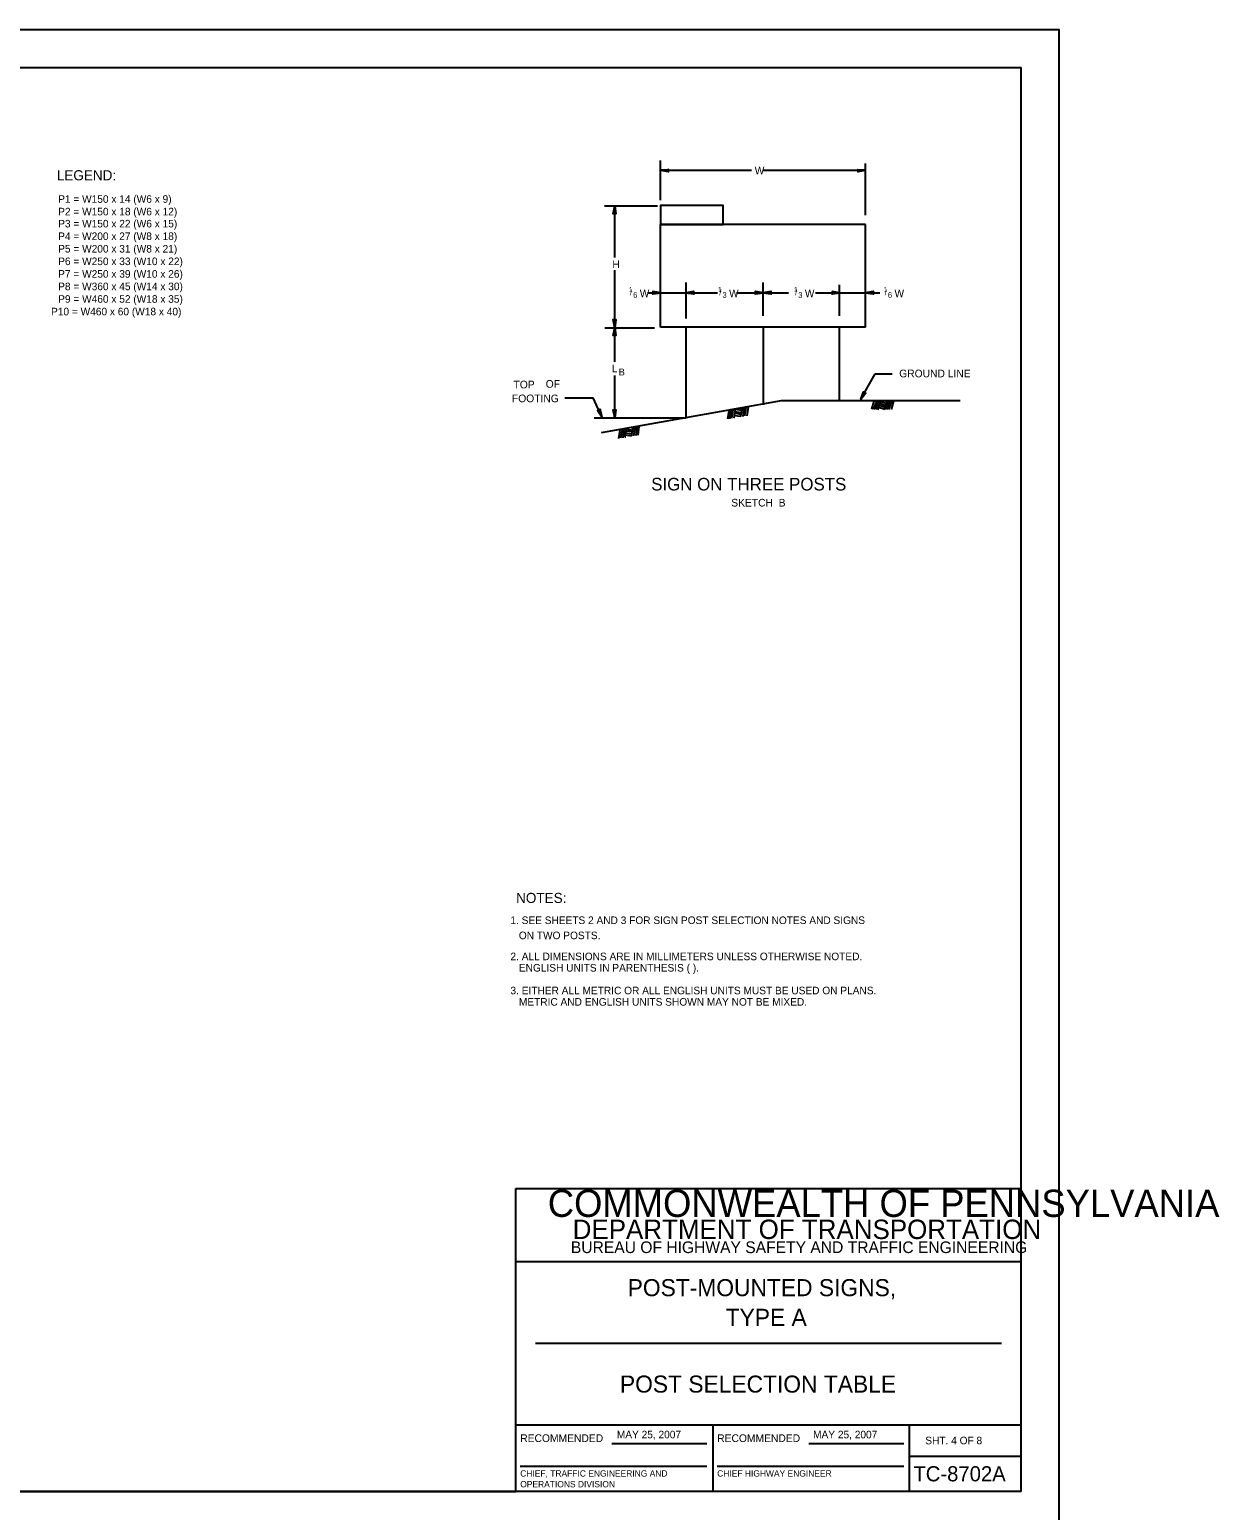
# Model space of a CAD drawing. Extents: x 637580 to 641008, y 294594 to 295782.
# Drawn here: x 640537 to 641008, y 295195 to 295782 of the extents above; entities that cross this region are included whole.
import ezdxf

# ---------------------------------------------------------------- set-up
doc = ezdxf.new("R2010")
doc.units = 0
for name, color, linetype in [('1', 7, 'Continuous'), ('2', 7, 'Continuous'), ('PLT-BNDY', 7, 'Continuous')]:
    doc.layers.add(name, color=color, linetype=linetype)

msp = doc.modelspace()

# ---------------------------------------------------------------- linework, layer by layer
at = {"layer": '1'}
for p, q in [((640143.31, 295766.63), (640929.31, 295766.63)), ((640929.31, 295202.63), (640929.31, 295766.63)), ((640786.58, 295714.03), (640786.58, 295729.78)), ((640786.58, 295725.9), (640822.58, 295725.9)), ((640827.21, 295725.9), (640867.71, 295725.9)), ((640867.71, 295708.15), (640867.71, 295728.65)), ((640764.33, 295711.78), (640785.33, 295711.78)), ((640768.46, 295691.4), (640768.46, 295711.78)), ((640786.58, 295663.78), (640786.58, 295704.4)), ((640867.71, 295704.4), (640786.58, 295704.4)), ((640867.71, 295663.78), (640867.71, 295704.4)), ((640768.46, 295663.53), (640768.46, 295686.4)), ((640796.71, 295667.15), (640796.71, 295681.4)), ((640827.21, 295668.28), (640827.21, 295681.4)), ((640857.46, 295668.28), (640857.46, 295680.53)), ((640781.33, 295677.4), (640786.58, 295677.4)), ((640786.58, 295677.4), (640796.21, 295677.4)), ((640796.71, 295677.4), (640809.08, 295677.4)), ((640816.58, 295677.4), (640827.21, 295677.4)), ((640827.21, 295677.4), (640837.21, 295677.4)), ((640847.96, 295677.4), (640857.46, 295677.4)), ((640857.46, 295677.4), (640867.71, 295677.4)), ((640867.71, 295677.4), (640873.46, 295677.4)), ((640764.46, 295663.53), (640784.21, 295663.53)), ((640768.46, 295650.03), (640768.46, 295663.53)), ((640867.71, 295663.78), (640786.58, 295663.78)), ((640796.71, 295627.9), (640796.71, 295663.78)), ((640827.21, 295663.78), (640827.21, 295633.03)), ((640857.46, 295634.4), (640857.46, 295663.78)), ((640768.46, 295627.9), (640768.46, 295644.65)), ((640865.83, 295635.28), (640871.58, 295645.28)), ((640871.58, 295645.28), (640878.33, 295645.28)), ((640748.71, 295635.78), (640759.83, 295635.78)), ((640763.33, 295628.28), (640759.83, 295635.78)), ((640834.33, 295634.53), (640763.08, 295621.9)), ((640816.08, 295631.28), (640815.58, 295627.9)), ((640818.71, 295631.65), (640818.21, 295628.4)), ((640818.71, 295631.4), (640818.33, 295631.53)), ((640819.58, 295631.9), (640819.08, 295628.4)), ((640820.33, 295631.9), (640819.83, 295628.65)), ((640821.21, 295632.15), (640820.71, 295628.65)), ((640905.21, 295634.53), (640834.33, 295634.53)), ((640871.08, 295634.4), (640870.08, 295631.28)), ((640872.08, 295634.4), (640870.83, 295631.15)), ((640872.83, 295634.4), (640871.71, 295631.15)), ((640873.71, 295634.4), (640872.46, 295631.15)), ((640872.96, 295631.15), (640872.58, 295631.28)), ((640875.33, 295631.15), (640872.83, 295631.9)), ((640875.46, 295631.9), (640873.08, 295632.78)), ((640875.71, 295632.65), (640873.46, 295633.53)), ((640876.08, 295633.4), (640873.71, 295634.28)), ((640876.33, 295634.4), (640875.33, 295631.15)), ((640876.33, 295634.28), (640875.83, 295634.4)), ((640877.08, 295634.4), (640876.08, 295631.15)), ((640878.08, 295634.4), (640876.83, 295631.15)), ((640878.83, 295634.4), (640877.83, 295631.15)), ((640760.33, 295627.9), (640796.71, 295627.9)), ((640813.58, 295630.78), (640813.08, 295627.4)), ((640814.33, 295631.03), (640813.83, 295627.53)), ((640815.21, 295631.03), (640814.71, 295627.78)), ((640815.96, 295628.03), (640815.58, 295628.03)), ((640818.33, 295628.4), (640815.71, 295628.65)), ((640818.33, 295629.15), (640815.83, 295629.65)), ((640818.46, 295629.9), (640815.96, 295630.28)), ((640818.58, 295630.78), (640816.08, 295631.15)), ((640770.46, 295623.03), (640769.96, 295619.65)), ((640771.33, 295623.15), (640770.71, 295619.78)), ((640772.08, 295623.4), (640771.58, 295619.9)), ((640772.96, 295623.53), (640772.33, 295620.15)), ((640772.83, 295620.15), (640772.46, 295620.15)), ((640775.08, 295620.65), (640772.58, 295621.03)), ((640775.08, 295621.4), (640772.71, 295621.78)), ((640775.33, 295622.28), (640772.83, 295622.53)), ((640775.46, 295622.9), (640772.96, 295623.4)), ((640775.58, 295623.9), (640774.96, 295620.65)), ((640775.58, 295623.9), (640775.08, 295623.9)), ((640776.33, 295624.03), (640775.83, 295620.78)), ((640777.21, 295624.28), (640776.71, 295620.9)), ((640777.96, 295624.4), (640777.58, 295621.03)), ((640729.31, 295202.63), (640729.31, 295322.63)), ((640729.31, 295322.63), (640929.31, 295322.63)), ((640929.31, 295293.63), (640729.31, 295293.63)), ((640737.06, 295261.31), (640921.56, 295261.31)), ((640729.31, 295229), (640929.31, 295229)), ((640807.31, 295229), (640807.31, 295202.63)), ((640885.19, 295202.63), (640885.19, 295229)), ((640767.24, 295221.57), (640804.87, 295221.57)), ((640845.24, 295221.57), (640882.87, 295221.57)), ((640885.19, 295216.63), (640929.31, 295216.63)), ((640730.99, 295212.68), (640804.87, 295212.68)), ((640808.99, 295212.68), (640882.87, 295212.68)), ((640929.31, 295202.63), (640143.31, 295202.63)), ((640143.31, 295202.63), (640729.31, 295202.63))]:
    msp.add_line(p, q, dxfattribs=at)
for points in [[(640789.58, 295725.4), (640789.33, 295725.65), (640786.58, 295725.9), (640789.58, 295725.4), (640789.71, 295725.28), (640786.58, 295725.9), (640789.33, 295725.9), (640789.46, 295726.03), (640786.58, 295725.9), (640789.71, 295726.28), (640789.46, 295726.03)], [(640864.71, 295726.03), (640864.83, 295725.9), (640867.71, 295725.9), (640864.71, 295726.03), (640864.71, 295726.28), (640867.71, 295725.9), (640864.83, 295725.65), (640864.83, 295725.4), (640867.71, 295725.9), (640864.71, 295725.28), (640864.83, 295725.4)], [(640767.96, 295708.9), (640768.21, 295708.9), (640768.46, 295711.78), (640767.96, 295708.9), (640767.83, 295708.65), (640768.46, 295711.78), (640768.58, 295708.9), (640768.71, 295708.9), (640768.46, 295711.78), (640768.83, 295708.65), (640768.71, 295708.9)], [(640783.58, 295677.9), (640783.71, 295677.65), (640786.58, 295677.4), (640783.58, 295677.9), (640783.46, 295677.9), (640786.58, 295677.4), (640783.71, 295677.28), (640783.58, 295677.03), (640786.58, 295677.4), (640783.46, 295676.9), (640783.58, 295677.03)], [(640799.58, 295677.03), (640799.46, 295677.28), (640796.71, 295677.4), (640799.58, 295677.03), (640799.71, 295676.9), (640796.71, 295677.4), (640799.46, 295677.65), (640799.58, 295677.9), (640796.71, 295677.4), (640799.71, 295677.9), (640799.58, 295677.9)], [(640824.21, 295677.9), (640824.33, 295677.65), (640827.21, 295677.4), (640824.21, 295677.9), (640824.08, 295677.9), (640827.21, 295677.4), (640824.33, 295677.28), (640824.21, 295677.03), (640827.21, 295677.4), (640824.08, 295676.9), (640824.21, 295677.03)], [(640830.21, 295677.03), (640829.96, 295677.28), (640827.21, 295677.4), (640830.21, 295677.03), (640830.33, 295676.9), (640827.21, 295677.4), (640829.96, 295677.65), (640830.21, 295677.9), (640827.21, 295677.4), (640830.33, 295677.9), (640830.21, 295677.9)], [(640854.58, 295677.9), (640854.71, 295677.65), (640857.46, 295677.4), (640854.58, 295677.9), (640854.46, 295677.9), (640857.46, 295677.4), (640854.71, 295677.28), (640854.58, 295677.03), (640857.46, 295677.4), (640854.46, 295676.9), (640854.58, 295677.03)], [(640870.71, 295677.03), (640870.58, 295677.28), (640867.71, 295677.4), (640870.71, 295677.03), (640870.83, 295676.9), (640867.71, 295677.4), (640870.58, 295677.65), (640870.71, 295677.9), (640867.71, 295677.4), (640870.83, 295677.9), (640870.71, 295677.9)], [(640768.83, 295666.53), (640768.58, 295666.4), (640768.46, 295663.53), (640768.83, 295666.53), (640768.83, 295666.78), (640768.46, 295663.53), (640768.21, 295666.4), (640767.96, 295666.53), (640768.46, 295663.53), (640767.83, 295666.78), (640767.96, 295666.53)], [(640767.96, 295660.65), (640768.21, 295660.78), (640768.46, 295663.53), (640767.96, 295660.65), (640767.83, 295660.53), (640768.46, 295663.53), (640768.58, 295660.78), (640768.71, 295660.65), (640768.46, 295663.53), (640768.83, 295660.53), (640768.71, 295660.65)], [(640867.71, 295637.65), (640867.33, 295637.65), (640865.83, 295635.28), (640867.71, 295637.65), (640867.83, 295637.65), (640865.83, 295635.28), (640867.08, 295637.78), (640866.96, 295638.03), (640865.83, 295635.28), (640866.96, 295638.15), (640866.96, 295638.03)], [(640762.46, 295631.03), (640762.33, 295630.78), (640763.33, 295628.28), (640762.46, 295631.03), (640762.46, 295631.28), (640763.33, 295628.28), (640762.08, 295630.65), (640761.71, 295630.65), (640763.33, 295628.28), (640761.58, 295630.78), (640761.71, 295630.65)], [(640768.83, 295630.9), (640768.58, 295630.78), (640768.46, 295627.9), (640768.83, 295630.9), (640768.83, 295631.03), (640768.46, 295627.9), (640768.21, 295630.78), (640767.96, 295630.78), (640768.46, 295627.9), (640767.83, 295631.03), (640767.96, 295630.78)]]:
    msp.add_lwpolyline(points, dxfattribs=at)
msp.add_lwpolyline([(640811.33, 295704.4), (640811.33, 295711.9), (640786.58, 295711.9), (640786.58, 295704.4)], close=True, dxfattribs=at)
at = {"layer": 'PLT-BNDY'}
msp.add_lwpolyline([(640103.31, 295781.63), (640944.31, 295781.63), (640944.31, 295187.63), (640103.31, 295187.63)], close=True, dxfattribs=at)

# ---------------------------------------------------------------- texts
at = {"layer": '1'}
for s, height, p in [('LEGEND:', 4.003, (640547.47, 295721.93)), ('W', 3.04, (640823.83, 295724.28)), ('P1 = W150 x 14 (W6 x 9)', 3, (640548, 295713.03)), ('P2 = W150 x 18 (W6 x 12)', 3, (640548, 295708.05)), ('P3 = W150 x 22 (W6 x 15)', 3, (640548, 295703.27)), ('P4 = W200 x 27 (W8 x 18)', 3, (640548, 295698.3)), ('P5 = W200 x 31 (W8 x 21)', 3, (640548, 295693.33)), ('P6 = W250 x 33 (W10 x 22)', 3, (640548, 295688.35)), ('H', 3.04, (640767.46, 295687.15)), ('P7 = W250 x 39 (W10 x 26)', 3, (640548, 295683.38)), ('P8 = W360 x 45 (W14 x 30)', 3, (640548, 295678.41)), ('1', 2, (640773.96, 295677.65)), ('/', 2.25, (640774.46, 295676.4)), ('W', 3, (640778.33, 295675.65)), ('1', 2, (640809.33, 295677.65)), ('/', 2.25, (640809.83, 295676.4)), ('W', 3, (640813.71, 295675.65)), ('1', 2, (640839.33, 295677.65)), ('/', 2.25, (640839.83, 295676.4)), ('W', 3, (640843.71, 295675.65)), ('1', 2, (640874.83, 295677.65)), ('/', 2.25, (640875.33, 295676.4)), ('W', 3, (640879.21, 295675.65)), ('P9 = W460 x 52 (W18 x 35)', 3, (640548, 295673.44)), ('6', 2.25, (640775.71, 295675.4)), ('3', 2.25, (640811.08, 295675.4)), ('3', 2.25, (640841.08, 295675.4)), ('6', 2.25, (640876.58, 295675.4)), ('P10 = W460 x 60 (W18 x 40)', 3, (640545.18, 295668.46)), ('L', 3.04, (640767.21, 295645.9)), ('B', 2.73, (640769.96, 295644.65)), ('GROUND LINE', 3.0427, (640881.08, 295643.9)), ('FOOTING', 3.044, (640727.71, 295634.03)), ('TOP', 3.043, (640728.33, 295639.53)), ('OF', 3.043, (640741.08, 295639.78)), ('SKETCH  B', 3.044, (640814.56, 295592.73)), (' 1. SEE SHEETS 2 AND 3 FOR SIGN POST SELECTION NOTES AND SIGNS', 3, (640725.97, 295427.37)), ('    ON TWO POSTS.', 3, (640725.97, 295421.37)), ('COMMONWEALTH OF PENNSYLVANIA', 10.7828, (640741.9, 295311.36)), ('DEPARTMENT OF TRANSPORTATION', 7.6837, (640751.76, 295302.61)), ('BUREAU OF HIGHWAY SAFETY AND TRAFFIC ENGINEERING', 4.6253, (640751.04, 295297.04)), ('POST-MOUNTED SIGNS,', 6.75, (640773.54, 295279.97)), ('TYPE A', 6.75, (640812.35, 295268.22)), ('POST SELECTION TABLE', 6.75, (640770.47, 295241.78)), ('RECOMMENDED', 3.048, (640730.99, 295222.2)), ('RECOMMENDED', 3.048, (640808.99, 295222.2)), ('SHT. 4 OF 8', 3, (640891.4, 295221.31)), ('CHIEF, TRAFFIC ENGINEERING AND', 2.5, (640730.99, 295208.51)), ('CHIEF HIGHWAY ENGINEER', 2.5, (640808.99, 295208.51)), ('TC-8702A', 6, (640886.68, 295206.63)), ('OPERATIONS DIVISION', 2.5, (640730.99, 295204.26))]:
    msp.add_text(s, height=height, dxfattribs=at).set_placement(p)
at = {"layer": '2'}
for s, height, p in [('SIGN ON THREE POSTS', 5, (640782.85, 295599.09)), ('NOTES:', 4.003, (640729.35, 295435.71)), (' 2. ALL DIMENSIONS ARE IN MILLIMETERS UNLESS OTHERWISE NOTED.', 3, (640726, 295413.04)), ('    ENGLISH UNITS IN PARENTHESIS ( ).', 3, (640726, 295408.54)), (' 3. EITHER ALL METRIC OR ALL ENGLISH UNITS MUST BE USED ON PLANS.', 3, (640726, 295399.54)), ('    METRIC AND ENGLISH UNITS SHOWN MAY NOT BE MIXED.     ', 3, (640726, 295395.04)), ('MAY 25, 2007', 3, (640769.25, 295223.67)), ('MAY 25, 2007', 3, (640846.97, 295223.67))]:
    msp.add_text(s, height=height, dxfattribs=at).set_placement(p)

doc.saveas('drawing.dxf')
